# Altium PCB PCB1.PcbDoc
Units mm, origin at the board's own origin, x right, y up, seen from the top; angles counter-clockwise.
Board outline 53 x 65 mm, 2 copper layers (Top Layer, Bottom Layer); 24 components, 24 nets, 100 pads, 123 vias.
Unrouted connection lines stored in the file: 16.
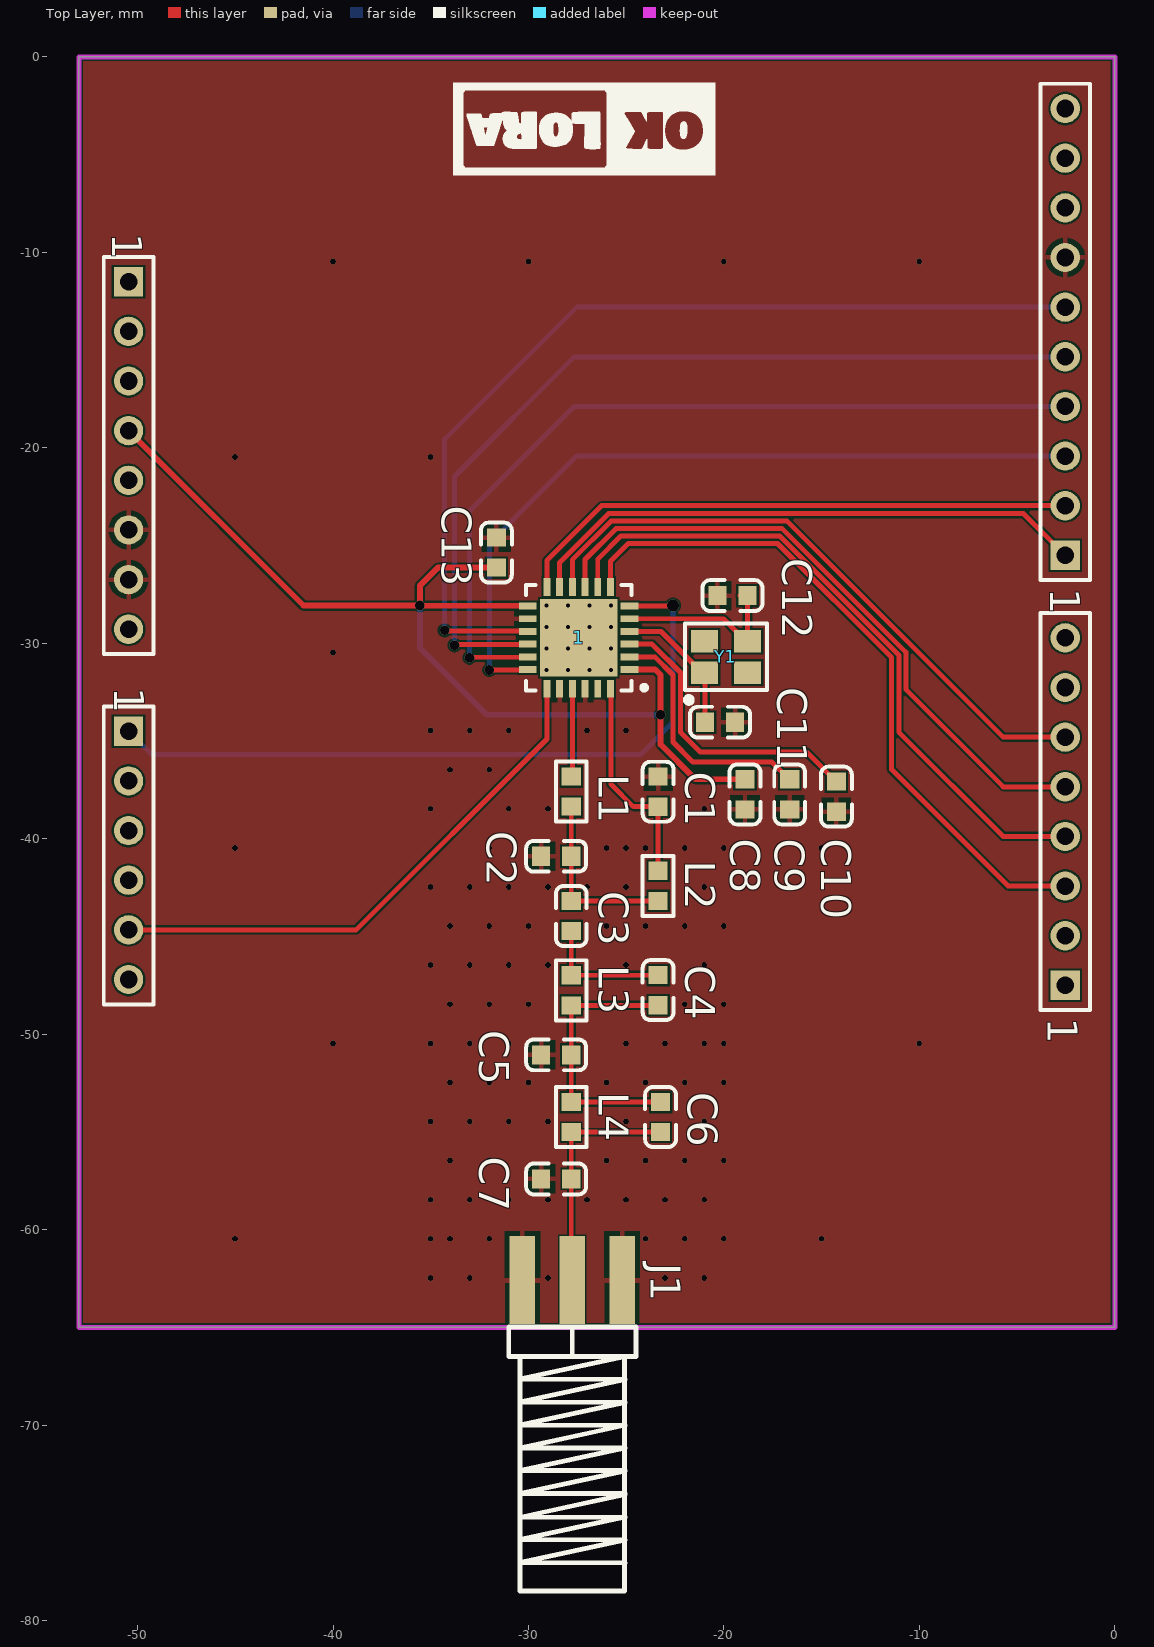
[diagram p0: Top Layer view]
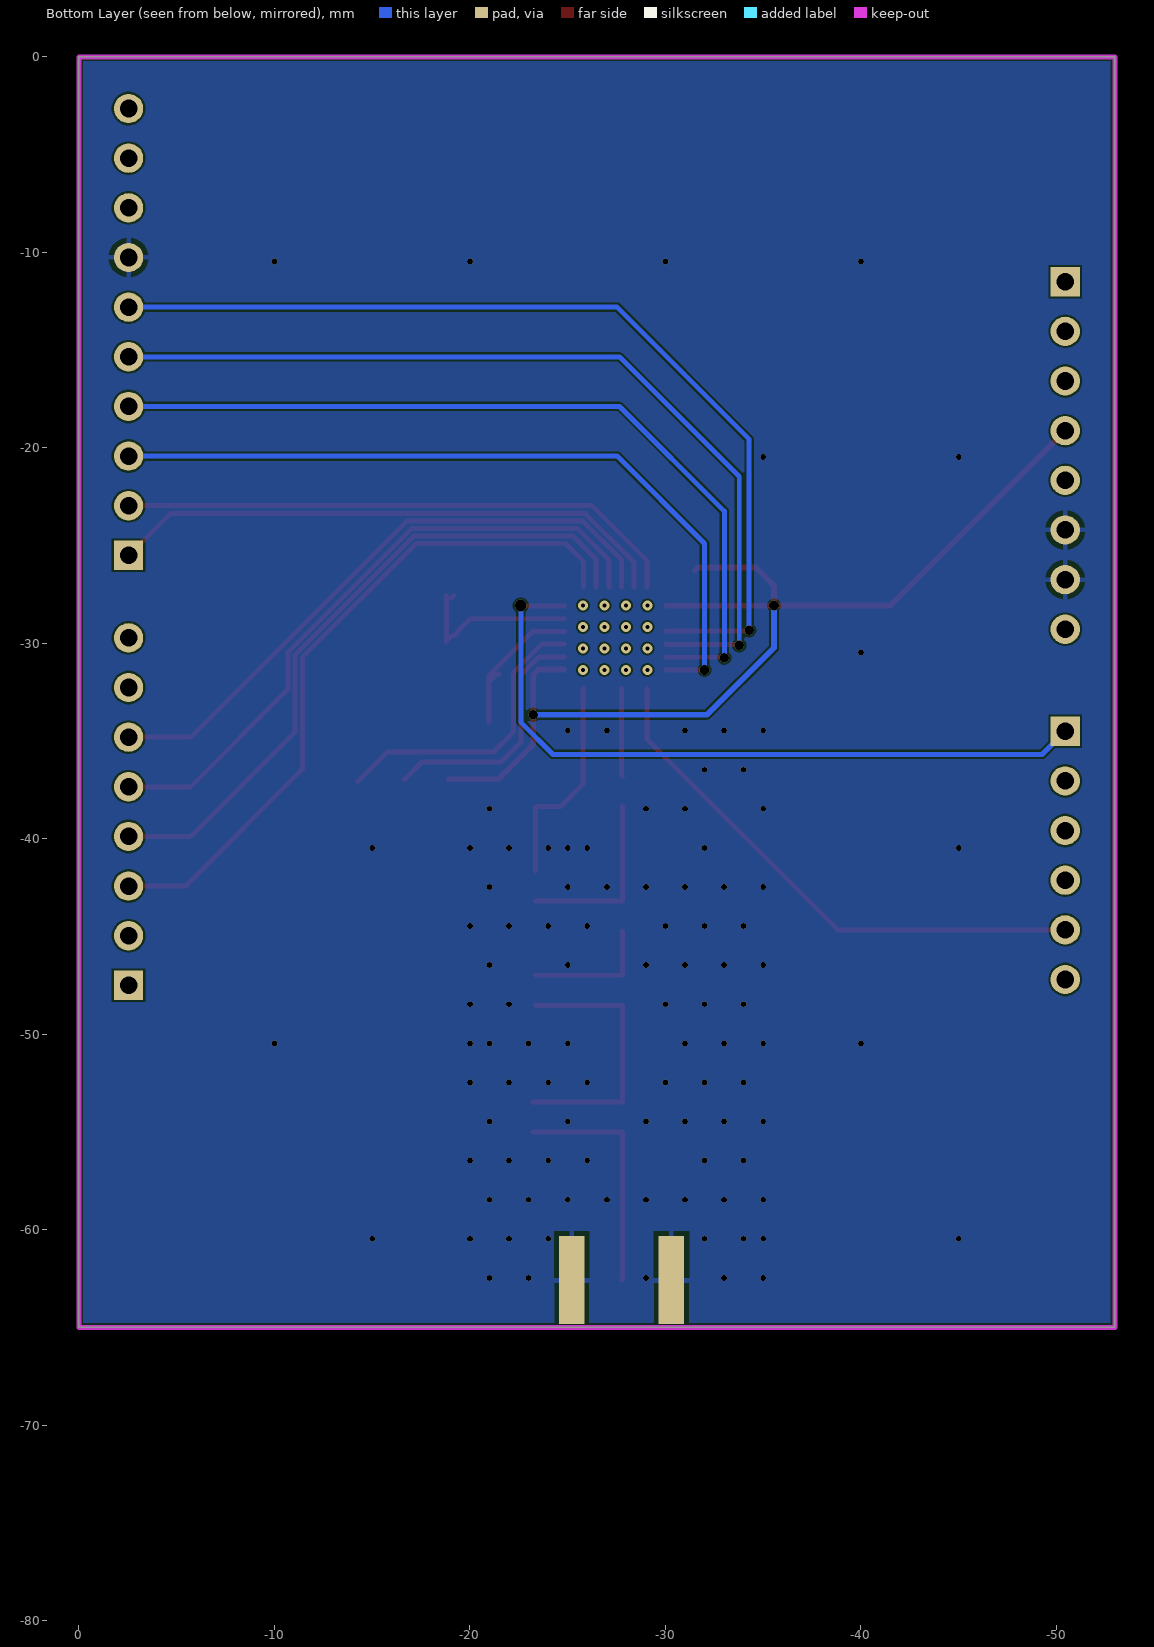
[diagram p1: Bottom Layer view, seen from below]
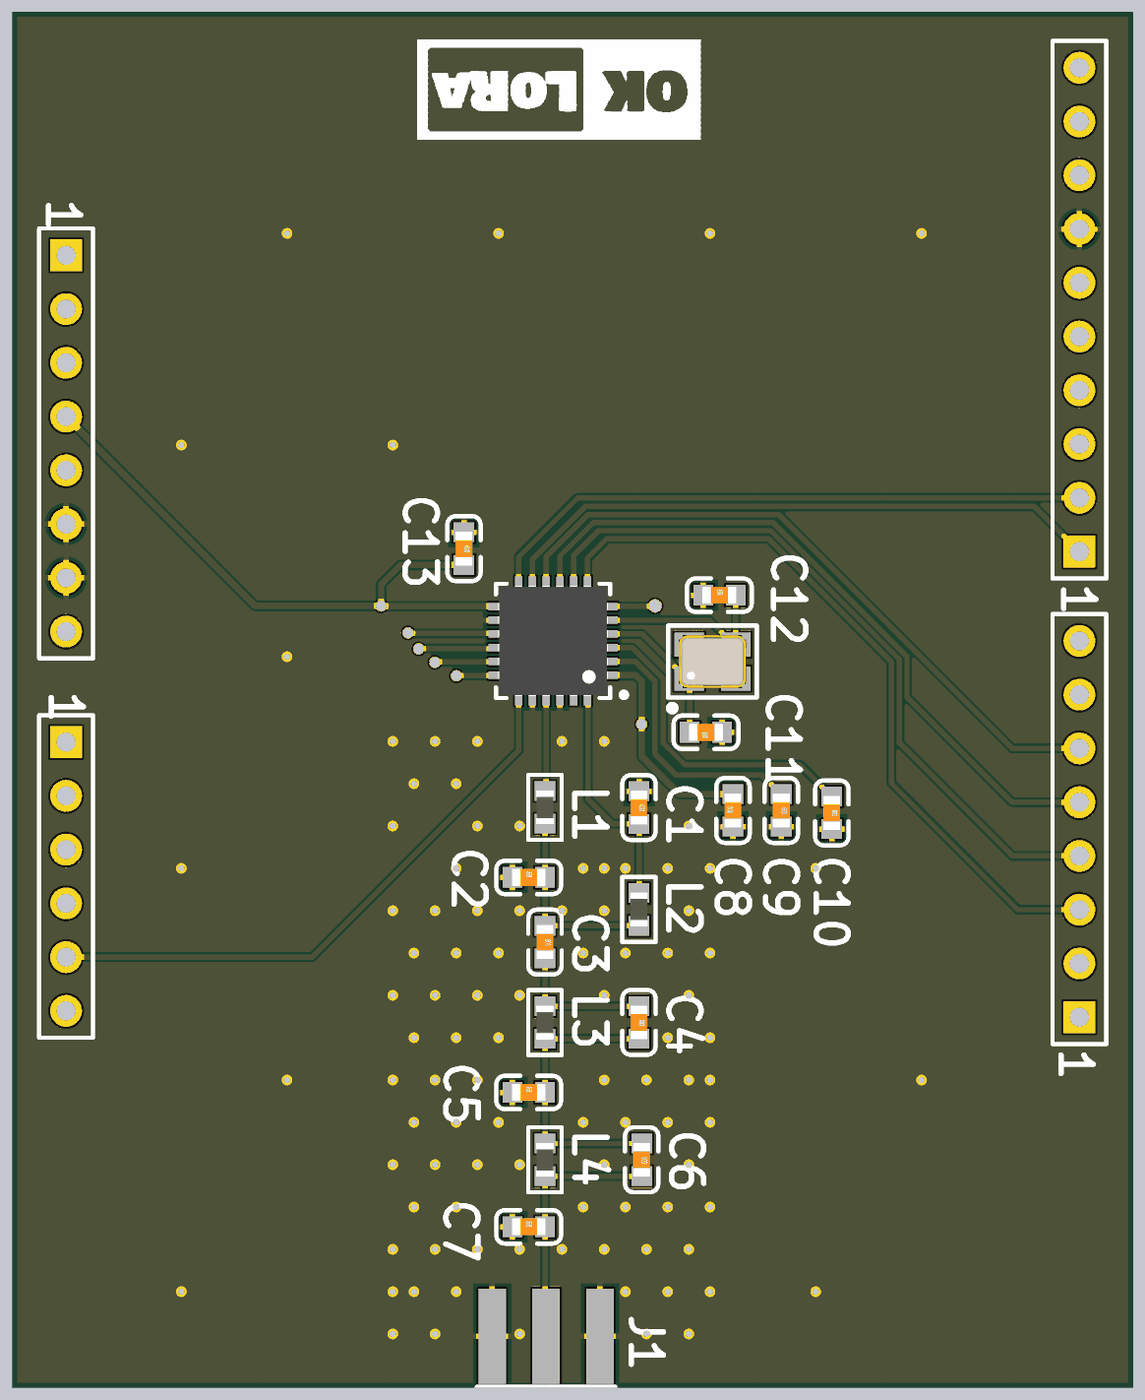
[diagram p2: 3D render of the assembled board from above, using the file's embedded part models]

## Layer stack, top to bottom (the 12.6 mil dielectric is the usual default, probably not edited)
Top Solder: solder mask 0.0102, Solder Resist, Dk 3.5
Top Layer: signal copper 0.0356
Dielectric 1: dielectric 0.32, FR-4, Dk 4.8
Bottom Layer: signal copper 0.0356
Bottom Solder: solder mask 0.0102, Solder Resist, Dk 3.5

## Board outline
-53,-65 -53,0 0,0 0,-65

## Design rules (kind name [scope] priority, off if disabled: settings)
Clearance [All] p1: gap=0.1 ignorepadtopadclearanceinfootprint=FALSE
PolygonConnect [All] p1: connectstyle=Relief reliefconductorwidth=0.254 reliefentries=4 polygonreliefangle="90 Angle" airgapwidth=0.254
RoutingVias [All] p1: holewidth=0.711 width=1.27 viastyle="Through Hole" minholewidth=0.711 minwidth=1.27 maxholewidth=0.711 maxwidth=1.27
SolderMaskExpansion [All] p1: expansion=0.102 istentingtop=FALSE
Width [All] p1: maxlimit=10 minlimit=0.1 preferedwidth=0.254
30 further rules are at their usual default settings.

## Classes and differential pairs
component class Sheet1: 1 C1 C2 C3 C4 C5 C6 C7 C8 C9 C10 C11 C12 C13 J1 L1 L2 L3 L4 Y1

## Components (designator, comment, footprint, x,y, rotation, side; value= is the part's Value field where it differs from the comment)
1 "Header 8" HDR1X8 -2.54,-47.5 r90 top (schematic designator P4)
1 "Header 10" HDR1X10 -2.54,-25.5 r90 top (schematic designator P3)
1 "Header 6" HDR1X6 -50.46,-34.5 r270 top (schematic designator P2)
1 "Header 8" HDR1X8 -50.46,-11.5 r270 top (schematic designator P1)
1 "SX1208" QFN65P510X510X100_HS-25M -27.432,-29.718 r180 top
C1 "10nF (103) 10% 50V" 0603_C -23.368,-37.592 r270 top
C2 "15pF (150) 5% 50V" 0603_C -28.583,-40.894 r0 top
C3 "22pF (220) 5% 50V" 0603_C -27.813,-43.95 r270 top
C4 "2.7pF (2R7) 0.25pF 50V" 0603_C -23.368,-47.744 r270 top
C5 "15pF (150) 5% 50V" 0603_C -28.583,-51.054 r0 top
C6 "2.7pF (2R7) 0.25pF 50V" 0603_C -23.241,-54.237 r270 top
C7 "8.2pF (8R2) 0.25pF 50V" 0603_C -28.583,-57.404 r0 top
C8 "100nF (104) 10% 50V" 0603_C -18.923,-37.727 r90 top
C9 "100nF (104) 10% 50V" 0603_C -16.637,-37.727 r270 top
C10 "100nF (104) 10% 50V" 0603_C -14.249,-37.846 r270 top
C11 "15pF (150) 5% 50V" 0603_C -20.201,-34.036 r180 top
C12 "15pF (150) 5% 50V" 0603_C -19.566,-27.559 r0 top
C13 "100nF (104) 10% 50V" 0603_C -31.644,-25.359 r270 top
J1 "RF_IO" PCBComponent_1 -27.813,-64.897 r180 top
L1 "10nH ±5%" 0603_L -27.813,-37.584 r270 top
L2 "33nH ±5%" 0603_L -23.368,-42.41 r90 top
L3 "12nH ±5%" 0603_L -27.813,-47.752 r270 top
L4 "10nH ±5%" 0603_L -27.813,-54.237 r270 top
Y1 "32MHZ 12PF 10PPM" SMD-3225_4P -19.896,-30.696 r0 top

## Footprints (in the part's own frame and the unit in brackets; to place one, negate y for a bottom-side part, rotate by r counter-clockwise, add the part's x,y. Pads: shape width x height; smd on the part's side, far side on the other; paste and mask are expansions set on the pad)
0603_C [mm]
  rect 0.93x0.98 smd: 1(-0.77,0) 2(0.77,0)
  silkscreen extent -1.53,-0.79 1.54,0.79, body extent -0.8,-0.4 0.8,0.4, height 0.3
0603_L [mm]
  rect 0.93x0.98 smd: 1(-0.77,0) 2(0.77,0)
  silkscreen extent -1.54,-0.79 1.53,0.79, body extent -0.82,-0.41 0.83,0.41, height 0.46
HDR1X6 [mm] "Connector; Header; 6 Position"
  rect 1.5x1.5 hole 0.9: 1(0,0)
  round 1.5 hole 0.9: 2(2.54,0) 3(5.08,0) 4(7.62,0) 5(10.16,0) 6(12.7,0)
  silkscreen extent -1.27,-1.27 13.97,1.27
HDR1X8 [mm] "Connector; Header; 8 Position"
  rect 1.5x1.5 hole 0.9: 1(0,0)
  round 1.5 hole 0.9: 2(2.54,0) 3(5.08,0) 4(7.62,0) 5(10.16,0) 6(12.7,0) 7(15.24,0) 8(17.78,0)
  silkscreen extent -1.27,-1.27 19.05,1.27
HDR1X10 [mm] "Connector; Header; 10 Position"
  rect 1.5x1.5 hole 0.9: 1(0,0)
  round 1.5 hole 0.9: 2(2.54,0) 3(5.08,0) 4(7.62,0) 5(10.16,0) 6(12.7,0) 7(15.24,0) 8(17.78,0) 9(20.32,0) 10(22.86,0)
  silkscreen extent -1.27,-1.27 24.13,1.27
PCBComponent_1 [mm]
  rect 1.3x4.5 smd: 1(-0.052,-2.322) 2(-2.602,-2.322) 2(2.498,-2.322)
  rect 1.3x4.5 smd far side: 2(-2.602,-2.322) 2(2.498,-2.322)
  silkscreen extent -3.3,0.09 3.2,13.59
QFN65P510X510X100_HS-25M [mm] "QFN, 24-Leads, Body 5.10x5.10mm, Pitch 0.65mm, Thermal Pad 3.95x3.95mm, IPC Low Density"
  rect 0.9x0.35 smd: 1(-2.6,1.625) 2(-2.6,0.975) 3(-2.6,0.325) 4(-2.6,-0.325) 5(-2.6,-0.975) 6(-2.6,-1.625) 13(2.6,-1.625) 14(2.6,-0.975) 15(2.6,-0.325) 16(2.6,0.325) 17(2.6,0.975) 18(2.6,1.625)
  rect 0.35x0.9 smd: 7(-1.625,-2.6) 8(-0.975,-2.6) 9(-0.325,-2.6) 10(0.325,-2.6) 11(0.975,-2.6) 12(1.625,-2.6) 19(1.625,2.6) 20(0.975,2.6) 21(0.325,2.6) 22(-0.325,2.6) 23(-0.975,2.6) 24(-1.625,2.6)
  rect 3.95x3.95 smd: 25(0,0)
  silkscreen extent -3.48,-2.7 2.7,2.7, body extent -2.6,-2.6 2.6,2.6, height 1
SMD-3225_4P [mm]
  rect 1.4x1.15 smd: 1(-1.1,-0.8) 2(1.1,-0.8) 3(1.1,0.8) 4(-1.1,0.8)
  silkscreen extent -2.1,-2.35 2.1,1.7, body extent -1.6,-1.25 1.6,1.25, height 0.61

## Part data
1 1: "Header, 8-Pin"
1: "Header, 10-Pin"
1: "Header, 6-Pin"
1: library part Component_1
C1: library part "0603 10nF (103) 10% 50V", "贴片电容", Package=0603, SuppliersPartNumber=C57112
C2 C5 C11 C12: library part "0603 15pF (150) 5% 50V", "贴片电容", Package=0603, SuppliersPartNumber=C1644
C3: library part "0603 22pF (220) 5% 50V", "贴片电容", Package=0603, SuppliersPartNumber=C1653
C4 C6: library part "0603 2.7pF (2R7) 0.25pF 50V", "贴片电容", Package=0603, SuppliersPartNumber=C16149
C7: library part "0603 8.2pF (8R2) 0.25pF 50V", "贴片电容", Package=0603, SuppliersPartNumber=C1685
C8 C9 C10 C13: library part "0603 100nF (104) 10% 50V", "贴片电容", Package=0603, SuppliersPartNumber=C14663
J1: library part SMB, "SMB Straight Connector"
L1 L4: library part "0603 10nH 5%", "贴片电感", Package=0603, SuppliersPartNumber=C15666
L2: library part "0603 33nH 5%", "贴片电感", Package=0603, SuppliersPartNumber=C35050
L3: library part "0603 12nH 5%", "贴片电感", Package=0603, SuppliersPartNumber=C29258
Y1: library part "SMD-3225_4P  25MHZ 12PF 10PPM", "贴片晶振", Package=SMD-3225_4P, SuppliersPartNumber=C9006

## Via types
v1: diameter 0.3, hole 0.3, Top Layer to Bottom Layer, 100 vias
v2: diameter 0.5, hole 0.2, Top Layer to Bottom Layer, 16 vias
v3: diameter 0.5, hole 0.5, Top Layer to Bottom Layer, 6 vias
v4: diameter 0.6, hole 0.6, Top Layer to Bottom Layer, 1 vias

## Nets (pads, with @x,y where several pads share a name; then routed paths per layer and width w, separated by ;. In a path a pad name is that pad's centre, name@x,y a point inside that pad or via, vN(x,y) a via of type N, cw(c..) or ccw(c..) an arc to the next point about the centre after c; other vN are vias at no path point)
DIO0: 1.3@-2.54,-42.42 1.7@-25.807,-27.118 | length 35.6
  Top Layer w0.254: 1.7@-25.807,-27.118 -25.807,-25.807 -24.892,-24.892 -17.257,-24.892 -11.43,-30.719 -11.43,-36.449 -5.459,-42.42 1.3@-2.54,-42.42
DIO1: 1.4@-2.54,-39.88 1.8@-26.457,-27.118 | length 34.5
  Top Layer w0.254: 1.8@-26.457,-27.118 -26.457,-25.695 -25.273,-24.511 -17.138,-24.511 -11.049,-30.6 -11.049,-34.544 -5.713,-39.88 1.4@-2.54,-39.88
DIO2: 1.5@-2.54,-37.34 1.9@-27.107,-27.118 | length 33.2
  Top Layer w0.254: 1.9@-27.107,-27.118 -27.107,-25.71 -25.527,-24.13 -17.018,-24.13 -10.695,-30.453 -10.695,-32.358 -5.713,-37.34 1.5@-2.54,-37.34
DIO3: 1.6@-2.54,-34.8 1.10@-27.757,-27.118 | length 32
  Top Layer w0.254: 1.10@-27.757,-27.118 -27.757,-25.725 -25.781,-23.749 -16.764,-23.749 -5.713,-34.8 1.6@-2.54,-34.8
DIO4: 1.1@-2.54,-25.5 1.11 | length 29
  Top Layer w0.254: 1.11 -28.407,-25.867 -25.908,-23.368 -4.672,-23.368 1.1@-2.54,-25.5
DIO5: 1.2@-2.54,-22.96 1.12 | length 29
  Top Layer w0.254: 1.12 -29.057,-25.755 -26.262,-22.96 1.2@-2.54,-22.96
GND: 1.6@-50.46,-24.2 1.7@-2.54,-10.26 1.7@-50.46,-26.74 1.14 1.20 1.22 C1.1 C2.1 C5.1 C7.1 C8.1 C9.2 C10.2 C11.1 C12.1 C13.1 J1.2
  other v1: -35.009,-62.466 -33.009,-62.466 -29.009,-62.466 -23.009,-62.466 -21.009,-62.466 -45.009,-60.466 -35.009,-60.466 -34.009,-60.466 -32.009,-60.466 -24.009,-60.466 -22.009,-60.466 -20.009,-60.466 -15.009,-60.466 -35.009,-58.466 -33.009,-58.466 -31.009,-58.466 -29.009,-58.466 -27.009,-58.466 -25.009,-58.466 -23.009,-58.466 -21.009,-58.466 -34.009,-56.466 -32.009,-56.466 -26.009,-56.466 -24.009,-56.466 -22.009,-56.466 -20.009,-56.466 -35.009,-54.466 -33.009,-54.466 -31.009,-54.466 -29.009,-54.466 -25.009,-54.466 -21.009,-54.466 -34.009,-52.466 -32.009,-52.466 -30.009,-52.466 -26.009,-52.466 -24.009,-52.466 -22.009,-52.466 -20.009,-52.466 -40.009,-50.466 -35.009,-50.466 -33.009,-50.466 -31.009,-50.466 -25.009,-50.466 -23.009,-50.466 -21.009,-50.466 -20.009,-50.466 -10.009,-50.466 -34.009,-48.466 -32.009,-48.466 -30.009,-48.466 -22.009,-48.466 -20.009,-48.466 -35.009,-46.466 -33.009,-46.466 -31.009,-46.466 -29.009,-46.466 -25.009,-46.466 -21.009,-46.466 -34.009,-44.466 -32.009,-44.466 -30.009,-44.466 -26.009,-44.466 -24.009,-44.466 -22.009,-44.466 -20.009,-44.466 -35.009,-42.466 -33.009,-42.466 -31.009,-42.466 -29.009,-42.466 -27.009,-42.466 -25.009,-42.466 -21.009,-42.466 -45.009,-40.466 -32.009,-40.466 -26.009,-40.466 -25.009,-40.466 -24.009,-40.466 -22.009,-40.466 -20.009,-40.466 -15.009,-40.466 -35.009,-38.466 -31.009,-38.466 -29.009,-38.466 -21.009,-38.466 -34.009,-36.466 -32.009,-36.466 -35.009,-34.466 -33.009,-34.466 -31.009,-34.466 -27.009,-34.466 -25.009,-34.466 -40.009,-30.466 -45.009,-20.466 -35.009,-20.466 -40.009,-10.466 -30.009,-10.466 -20.009,-10.466 -10.009,-10.466
MISO: 1.5@-2.54,-15.34 1.16 | length 46.2
  Top Layer w0.254: v3(-33.782,-30.099) -33.754,-30.071 -30.06,-30.071 1.16
  Bottom Layer w0.254: v3(-33.782,-30.099) -33.782,-21.463 -27.659,-15.34 1.5@-2.54,-15.34
MOSI: 1.4@-2.54,-17.88 1.17 | length 43.2
  Top Layer w0.254: v3(-33.02,-30.734) -32.999,-30.713 -30.053,-30.713 1.17
  Bottom Layer w0.254: v3(-33.02,-30.734) -33.02,-23.241 -27.659,-17.88 1.4@-2.54,-17.88
Net1_2: 1.2@-24.832,-30.693 C9.1 | length 12.8
  Top Layer w0.254: 1.2@-24.832,-30.693 -23.536,-30.693 -22.606,-31.623 -22.606,-35.052 -21.59,-36.068 -17.551,-36.068 -16.662,-36.957 C9.1
  other v2: -29.082,-31.368 -27.982,-31.368 -26.882,-31.368 -25.782,-31.368 -29.082,-30.268 -27.982,-30.268 -26.882,-30.268 -25.782,-30.268 -29.082,-29.168 -27.982,-29.168 -26.882,-29.168 -25.782,-29.168 -29.082,-28.068 -27.982,-28.068 -26.882,-28.068 -25.782,-28.068
Net1_3: 1.3@-24.832,-30.043 C10.1 | length 15.3
  Top Layer w0.254: 1.3@-24.832,-30.043 -23.678,-30.043 -22.225,-31.496 -22.225,-34.544 -21.209,-35.56 -15.765,-35.56 C10.1
Net1_4: 1.4@-24.832,-29.393 C11.2 Y1.1 | length 7.7
  Top Layer w0.254: 1.4@-24.832,-29.393 -23.224,-29.393 -20.971,-31.646 C11.2 ; Y1.1@-21.502,-31.572 -21.377,-31.572 Y1.1@-21.098,-31.851
Net1_5: 1.5@-24.832,-28.743 C12.2 Y1.3 | length 9
  Top Layer w0.254: 1.5@-24.832,-28.743 -20.025,-28.743 -19.369,-29.399 -19.369,-29.448 -19.226,-29.591 -19.177,-29.591 Y1.3@-19.101,-29.591 ; C12.2@-19.177,-27.559 C12.2@-19.05,-27.686 ; Y1.3@-19.05,-29.642 Y1.3 C12.2
Net1_21: 1.21 L1.1 | length 4.5
  Top Layer w0.254: L1.1 -27.757,-36.758 1.21
Net1_24: 1.24 C1.2 L2.2 | length 11.1
  Top Layer w0.254: 1.24 -25.781,-32.344 -25.781,-37.211 -24.638,-38.354 -23.376,-38.354 C1.2 L2.2
NetC2_2: C2.2 C3.1 L1.2 L2.1 | length 9.3
  Top Layer w0.254: L1.2 C2.2 C3.1 L2.1
NetC3_2: C3.2 C4.1 L3.1 | length 6.7
  Top Layer w0.254: C3.2 L3.1 -23.376,-46.982 C4.1
NetC4_2: C4.2 C5.2 C6.1 L3.2 L4.1 | length 14
  Top Layer w0.254: C4.2 -23.376,-48.522 L3.2 C5.2 L4.1 C6.1
NetC6_2: C6.2 C7.2 J1.1 L4.2 | length 12.2
  Top Layer w0.254: J1.1 -27.813,-62.523 C7.2 L4.2 C6.2
NSS: 1.3@-2.54,-20.42 1.18 | length 39.8
  Top Layer w0.254: v3(-32.004,-31.369) -31.991,-31.356 -30.045,-31.356 1.18
  Bottom Layer w0.254: v3(-32.004,-31.369) -32.004,-24.892 -27.532,-20.42 1.3@-2.54,-20.42
RESET: 1.1@-50.46,-34.5 1.6@-24.832,-28.093 | length 37.2
  Top Layer w0.254: 1.6@-24.832,-28.093 -24.819,-28.08 -22.619,-28.08 v4(-22.606,-28.067)
  Bottom Layer w0.254: 1.1@-50.46,-34.5 -49.273,-35.687 -24.257,-35.687 -22.606,-34.036 v4(-22.606,-28.067)
RXTX: 1.5@-50.46,-44.66 1.19 | length 28
  Top Layer w0.254: 1.5@-50.46,-44.66 -38.818,-44.66 -29.057,-34.899 1.19
SCK: 1.6@-2.54,-12.8 1.15 | length 48.6
  Top Layer w0.254: v3(-34.29,-29.337) -34.262,-29.365 -30.06,-29.365 1.15
  Bottom Layer w0.254: v3(-34.29,-29.337) -34.29,-19.558 -27.532,-12.8 1.6@-2.54,-12.8
VBAT: 1.1@-24.832,-31.343 1.4@-50.46,-19.12 1.13 C8.2 C13.2 | length 55.9
  Top Layer w0.254: v3(-35.56,-28.067) v3@-35.547,-28.08 ; C13.2 C13.2@-31.497,-26.276 ; 1.13@-30.045,-28.08 1.13
  Top Layer w0.3: 1.4@-50.46,-19.12 -41.513,-28.067 v3(-35.56,-28.067) -35.56,-27.051 -34.638,-26.129 C13.2 ; v3@-35.547,-28.08 1.13@-30.045,-28.08 ; 1.1@-24.832,-31.343 -23.521,-31.343 -23.241,-31.623 v3(-23.241,-33.655) -23.241,-35.179 -21.463,-36.957 C8.2
  Bottom Layer w0.3: v3(-35.56,-28.067) -35.56,-30.226 -32.131,-33.655 v3(-23.241,-33.655)
pads on no net: 1.1@-2.54,-47.5 1.1@-50.46,-11.5 1.2@-2.54,-44.96 1.2@-50.46,-14.04 1.2@-50.46,-37.04 1.3@-50.46,-16.58 1.3@-50.46,-39.58 1.4@-50.46,-42.12 1.5@-50.46,-21.66 1.6@-50.46,-47.2 1.7@-2.54,-32.26 1.8@-2.54,-7.72 1.8@-2.54,-29.72 1.8@-50.46,-29.28 1.9@-2.54,-5.18 1.10@-2.54,-2.64 1.23 1.25 Y1.2 Y1.4

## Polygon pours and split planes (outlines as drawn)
GND on Top Layer "GND_L01_P000" (solid, pour order 0): 0,0 0,-65.024 -52.959,-65.024 -52.959,0
GND on Bottom Layer "GND_L02_P001" (solid, pour order 1): -52.959,-64.897 0,-64.897 0,0 -52.959,0

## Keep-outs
Keep-Out Layer:
  the board outline again, w0.254

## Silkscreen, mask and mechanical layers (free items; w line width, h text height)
Top Overlay:
  drawing of 936 lines, arcs and shapes, not listed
